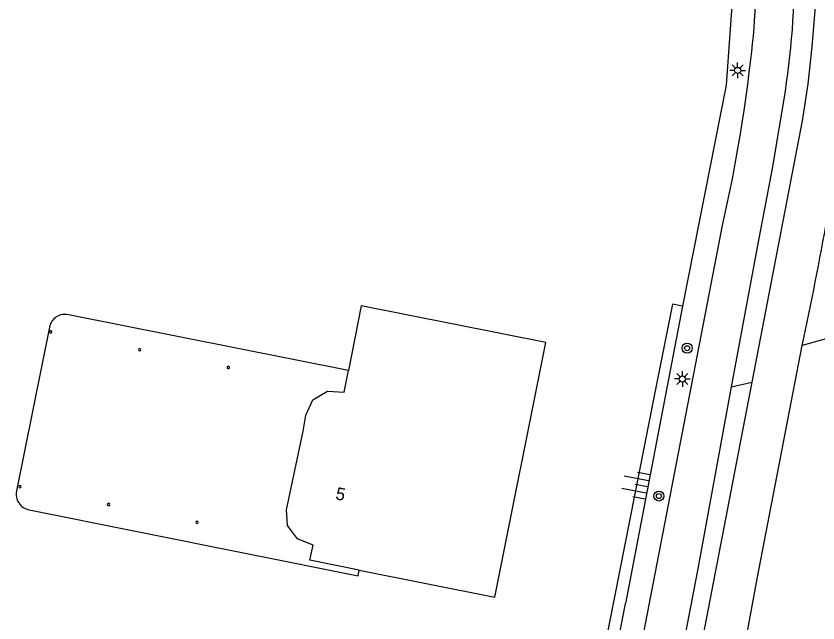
# Model space of a CAD drawing. Extents: x 131000 to 133013, y 393000 to 396501.
# Drawn here: x 131310.4 to 131374.7, y 394257.8 to 394306.4 of the extents above; entities that cross this region are included whole.
import ezdxf

# ---------------------------------------------------------------- set-up
doc = ezdxf.new("R2010")
doc.units = 0
for name, color, linetype in [('gg-afsc-hekwerk', 7, 'Continuous'), ('gg-anno-huisnummerreeks BGT', 7, 'Continuous'), ('gg-bbg-hoofdgebouw', 7, 'Continuous'), ('gg-bbg-luifel en loopbrug', 7, 'Continuous'), ('gg-bbg-pilaar overkapping', 7, 'Continuous'), ('gg-knt-BGT kruinlijn', 7, 'Continuous'), ('gg-knt-verharding', 7, 'Continuous'), ('gg-kntw-bovenkant insteek waterloop', 7, 'Continuous'), ('gt-grn-groengrens', 7, 'Continuous'), ('gt-symb-boom', 7, 'Continuous'), ('gt-symb-lichtmast', 7, 'Continuous'), ('gt-symb-talud symbool', 7, 'Continuous')]:
    doc.layers.add(name, color=color, linetype=linetype)

# ---------------------------------------------------------------- blocks, each defined once
blk = doc.blocks.new('gt0-LMAST')
at = {"layer": 'gt-symb-lichtmast'}
for p, q in [((-0.182, 0.173), (-0.447, 0.438)), ((-0.005, 0.246), (-0.005, 0.621)), ((0.172, 0.173), (0.437, 0.438)), ((-0.255, -0.004), (-0.63, -0.004)), ((-0.182, -0.181), (-0.447, -0.446)), ((-0.005, -0.254), (-0.005, -0.629)), ((0.437, -0.446), (0.172, -0.181)), ((0.245, -0.004), (0.62, -0.004))]:
    blk.add_line(p, q, dxfattribs=at)
blk.add_circle((-0.005, -0.004), 0.25, dxfattribs=at)
blk = doc.blocks.new('gt0-BOOM')
at = {"layer": 'gt-symb-boom'}
for radius in [0.4, 0.2]:
    blk.add_circle((0, 0), radius, dxfattribs=at)
blk = doc.blocks.new('gt0-TALUD_1')
at = {"layer": 'gt-symb-talud symbool'}
for p, q in [((-1, -1), (-1, 0)), ((-0.5, -2), (-0.5, 0)), ((0, -1), (0, 0)), ((0.5, -2), (0.5, 0)), ((1, -1), (1, 0))]:
    blk.add_line(p, q, dxfattribs=at)

msp = doc.modelspace()

# ---------------------------------------------------------------- linework, layer by layer
at = {"layer": 'gg-afsc-hekwerk'}
msp.add_line((131363.838, 394283.201), (131363.055, 394283.352), dxfattribs=at)
for points in [[(131366.988, 394369.762), (131362.827, 394345.526), (131362.906, 394342.513), (131363.383, 394336.516), (131363.903, 394333.549), (131364.496, 394330.605), (131365.166, 394327.676), (131365.939, 394324.768), (131366.676, 394321.854), (131367.189, 394318.884), (131367.55, 394315.902), (131367.795, 394312.899), (131367.811, 394309.89), (131367.783, 394306.884), (131367.348, 394300.889), (131363.838, 394283.201)], [(131363.055, 394283.352), (131361.593, 394276.134), (131353.631, 394235.828)]]:
    msp.add_lwpolyline(points, dxfattribs=at)
at = {"layer": 'gg-bbg-hoofdgebouw'}
for points in [[(131337.944, 394262.047), (131348.802, 394259.868), (131352.895, 394280.265), (131338.108, 394283.214), (131337.074, 394278.03)], [(131337.944, 394262.047), (131333.995, 394262.839), (131334.262, 394264.054), (131332.995, 394264.541), (131332.199, 394265.618), (131332.117, 394266.88), (131333.441, 394273.19), (131333.658, 394274.469), (131334.23, 394275.685), (131335.396, 394276.386), (131336.73, 394276.305), (131337.074, 394278.03)]]:
    msp.add_lwpolyline(points, dxfattribs=at)
at = {"layer": 'gg-bbg-luifel en loopbrug'}
for p, q in [((131337.074, 394278.03), (131314.64, 394282.496)), ((131313.119, 394281.515), (131310.471, 394268.4))]:
    msp.add_line(p, q, dxfattribs=at)
msp.add_lwpolyline([(131311.489, 394266.875), (131337.851, 394261.581), (131337.944, 394262.047)], dxfattribs=at)
for centre, radius, start, end in [((131314.355, 394281.268), 1.26, 76.92205, 168.71958), ((131311.739, 394268.144), 1.293, 168.58228, 258.86719)]:
    msp.add_arc(centre, radius, start, end, dxfattribs=at)
at = {"layer": 'gg-bbg-pilaar overkapping'}
for centre, radius, start, end in [((131313.221, 394281.131), 0.099, 359.99708, 180.00292), ((131313.221, 394281.131), 0.099, 179.99708, 0.00292), ((131320.345, 394279.707), 0.1, 0, 180), ((131320.345, 394279.707), 0.1, 180, 0), ((131327.455, 394278.279), 0.099, 359.99708, 180.00292), ((131327.455, 394278.279), 0.099, 179.99708, 0.00292), ((131310.756, 394268.726), 0.1, 0, 180), ((131310.756, 394268.726), 0.1, 180, 0), ((131317.858, 394267.302), 0.1, 0, 180), ((131317.858, 394267.302), 0.1, 180, 0), ((131324.94, 394265.873), 0.1, 0, 180), ((131324.94, 394265.873), 0.1, 180, 0)]:
    msp.add_arc(centre, radius, start, end, dxfattribs=at)
at = {"layer": 'gg-knt-BGT kruinlijn'}
msp.add_line((131363.838, 394283.201), (131359.278, 394259.369), dxfattribs=at)
msp.add_lwpolyline([(131349.359, 394209.793), (131350.427, 394213.777), (131359.278, 394259.369)], dxfattribs=at)
at = {"layer": 'gg-knt-verharding'}
for points in [[(131367.778, 394276.719), (131369.871, 394288.044), (131371.064, 394294.21), (131372.085, 394300.407)], [(131327.328, 394103.313), (131341.345, 394163.261), (131349.669, 394201.132), (131354.55, 394225.005), (131367.045, 394289.642)], [(131348.357, 394180.818), (131349.26, 394184.877), (131351.941, 394197.172), (131354.562, 394209.479), (131357.306, 394222.713), (131359.986, 394235.961), (131362.556, 394248.985), (131365.063, 394262.022), (131367.778, 394276.719)]]:
    msp.add_lwpolyline(points, dxfattribs=at)
for centre, radius, start, end in [((131306.562, 394310.457), 63.21, 352.0396, 1.16592), ((131303.637, 394310.695), 69.217, 351.45211, 0.80697), ((131251.635, 394316.125), 118.41, 347.076, 353.00399)]:
    msp.add_arc(centre, radius, start, end, dxfattribs=at)
at = {"layer": 'gg-kntw-bovenkant insteek waterloop'}
for points in [[(131374.549, 394310.455), (131374.465, 394307.201), (131374.203, 394303.956), (131373.879, 394300.991), (131373.438, 394298.041), (131369.402, 394277.113)], [(131332.471, 394091.459), (131354.333, 394184.204), (131356.47, 394194.225), (131358.532, 394204.261), (131360.328, 394213.45), (131362.182, 394222.628), (131364.253, 394232.104), (131366.2, 394241.607), (131369.839, 394261.342), (131373.421, 394280.027)], [(131369.402, 394277.113), (131361.008, 394233.587), (131349.386, 394180.743)]]:
    msp.add_lwpolyline(points, dxfattribs=at)
msp.add_arc((131131.763, 394333.099), 247.417, 347.61347, 352.44254, dxfattribs=at)
at = {"layer": 'gt-grn-groengrens'}
for p, q in [((131381.66, 394282.355), (131373.421, 394280.027)), ((131367.778, 394276.719), (131369.402, 394277.113))]:
    msp.add_line(p, q, dxfattribs=at)

# ---------------------------------------------------------------- block references
at = {"layer": 'gt-symb-boom'}
for p in [(131364.217, 394279.824), (131361.952, 394267.981)]:
    msp.add_blockref('gt0-BOOM', p, dxfattribs=at)
at = {"layer": 'gt-symb-lichtmast'}
for p in [(131368.261, 394302.071), (131363.842, 394277.361)]:
    msp.add_blockref('gt0-LMAST', p, dxfattribs=at)
at = {"layer": 'gt-symb-talud symbool', "xscale": 1.0002569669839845, "yscale": 1.0002569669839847, "rotation": -100.65836150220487}
msp.add_blockref('gt0-TALUD_1', (131361.032, 394268.736), dxfattribs=at)

# ---------------------------------------------------------------- texts
at = {"layer": 'gg-anno-huisnummerreeks BGT'}
msp.add_text('5', height=1, rotation=348.2, dxfattribs=at).set_placement((131335.986, 394267.729))

doc.saveas('drawing.dxf')
